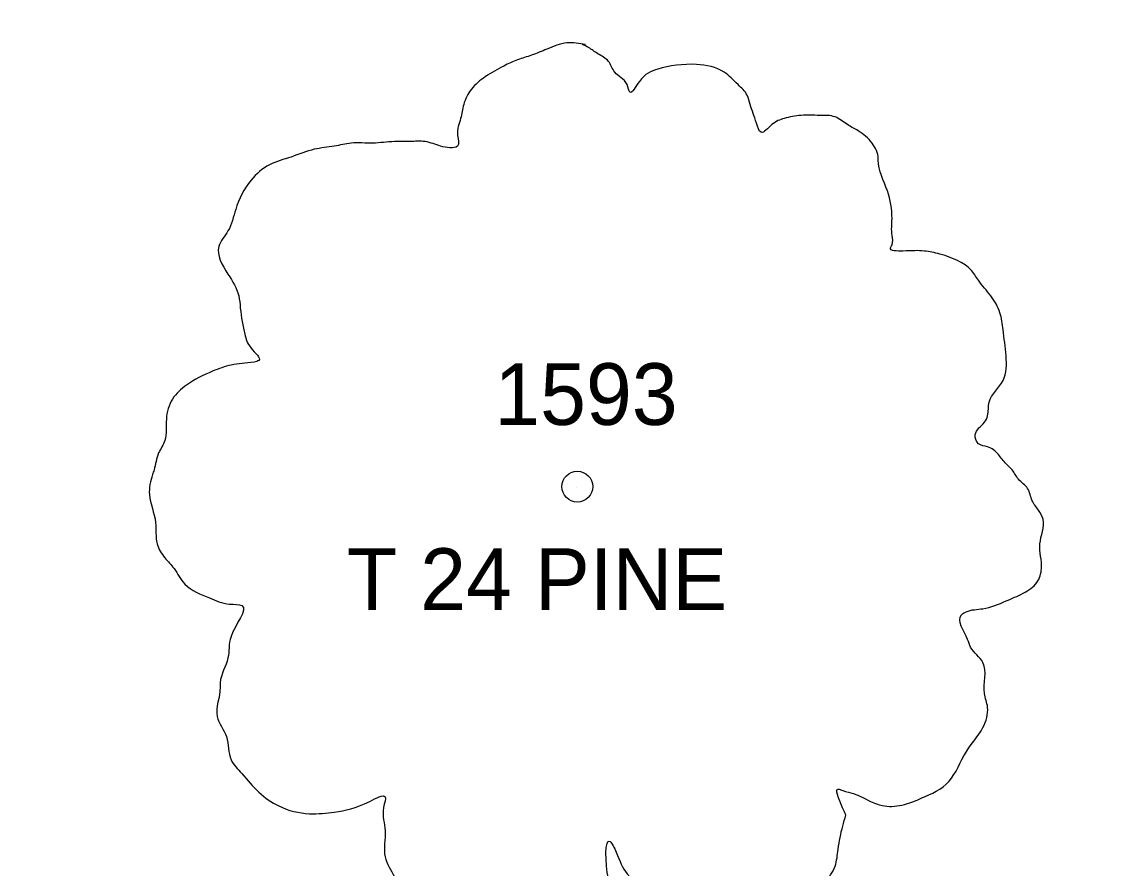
# Model space of a CAD drawing. Extents: x 1964982 to 1970452, y 1116335 to 1119906.
# Drawn here: x 1966640.09 to 1966657.58, y 1117463.46 to 1117477.19 of the extents above; entities that cross this region are included whole.
import ezdxf

# ---------------------------------------------------------------- set-up
doc = ezdxf.new("R2010")
doc.units = 0
for name, color, linetype in [('RD_EX_VEG', 7, 'Continuous'), ('RD_EX_VEG_txCode', 7, 'Continuous'), ('RD_HC_CL_Rel', 7, 'Continuous'), ('RD_PD_Final_TrvlWay', 7, 'Continuous')]:
    doc.layers.add(name, color=color, linetype=linetype)

msp = doc.modelspace()

# ---------------------------------------------------------------- linework, layer by layer
at = {"layer": 'RD_EX_VEG'}
for centre, radius in [((1966649.1, 1117469.652), 0.25), ((1966649.1, 1117469.652), 0.25), ((1966649.087, 1117469.633), 0.0001), ((1966649.087, 1117469.633), 0.0001)]:
    msp.add_circle(centre, radius, dxfattribs=at)
for points in [[(1966649.232, 1117476.819), (1966648.932, 1117476.844), (1966648.607, 1117476.744), (1966648.357, 1117476.645), (1966648.132, 1117476.57), (1966647.907, 1117476.47), (1966647.607, 1117476.295), (1966647.382, 1117476.095), (1966647.257, 1117475.845), (1966647.207, 1117475.62), (1966647.158, 1117475.345), (1966647.158, 1117475.17), (1966647.033, 1117475.145), (1966646.883, 1117475.17), (1966646.633, 1117475.245), (1966646.383, 1117475.245), (1966646.133, 1117475.245), (1966645.783, 1117475.22), (1966645.433, 1117475.22), (1966645.158, 1117475.17), (1966644.834, 1117475.12), (1966644.459, 1117474.995), (1966644.109, 1117474.87), (1966643.809, 1117474.62), (1966643.559, 1117474.146), (1966643.434, 1117473.796), (1966643.284, 1117473.546), (1966643.434, 1117473.096), (1966643.609, 1117472.746), (1966643.634, 1117472.546), (1966643.709, 1117472.122), (1966643.809, 1117471.897), (1966643.934, 1117471.697), (1966643.859, 1117471.672), (1966643.484, 1117471.622), (1966643.184, 1117471.522), (1966642.759, 1117471.297), (1966642.535, 1117471.072), (1966642.435, 1117470.747), (1966642.41, 1117470.397), (1966642.31, 1117470.197), (1966642.235, 1117469.922), (1966642.21, 1117469.847), (1966642.16, 1117469.523), (1966642.26, 1117469.073), (1966642.285, 1117468.723), (1966642.41, 1117468.498), (1966642.56, 1117468.323), (1966642.734, 1117468.073), (1966643.134, 1117467.848), (1966643.459, 1117467.748), (1966643.659, 1117467.723), (1966643.484, 1117467.224), (1966643.434, 1117466.874), (1966643.309, 1117466.474), (1966643.309, 1117466.399), (1966643.259, 1117465.924), (1966643.409, 1117465.599), (1966643.484, 1117465.225), (1966643.659, 1117465), (1966643.934, 1117464.7), (1966644.259, 1117464.475), (1966644.759, 1117464.35), (1966645.158, 1117464.375), (1966645.733, 1117464.55), (1966645.983, 1117464.625), (1966645.958, 1117464.45), (1966645.983, 1117464.075), (1966645.983, 1117463.65), (1966646.133, 1117463.325), (1966646.233, 1117463.05), (1966646.383, 1117462.801), (1966646.708, 1117462.576), (1966647.108, 1117462.501), (1966647.532, 1117462.351), (1966647.982, 1117462.276), (1966648.482, 1117462.251), (1966649.082, 1117462.401), (1966649.357, 1117462.526), (1966649.457, 1117462.701), (1966649.656, 1117463.075), (1966649.606, 1117463.3), (1966649.631, 1117463.9), (1966649.731, 1117463.725), (1966649.906, 1117463.375), (1966650.406, 1117463.075), (1966650.806, 1117462.901), (1966651.281, 1117462.751), (1966651.581, 1117462.676), (1966652.055, 1117462.751), (1966652.43, 1117462.826), (1966652.805, 1117462.951), (1966653.105, 1117463.225), (1966653.28, 1117463.5), (1966653.33, 1117463.775), (1966653.405, 1117464.15), (1966653.455, 1117464.325)], [(1966649.232, 1117476.819), (1966648.932, 1117476.844), (1966648.607, 1117476.744), (1966648.357, 1117476.645), (1966648.132, 1117476.57), (1966647.907, 1117476.47), (1966647.607, 1117476.295), (1966647.382, 1117476.095), (1966647.257, 1117475.845), (1966647.207, 1117475.62), (1966647.158, 1117475.345), (1966647.158, 1117475.17), (1966647.033, 1117475.145), (1966646.883, 1117475.17), (1966646.633, 1117475.245), (1966646.383, 1117475.245), (1966646.133, 1117475.245), (1966645.783, 1117475.22), (1966645.433, 1117475.22), (1966645.158, 1117475.17), (1966644.834, 1117475.12), (1966644.459, 1117474.995), (1966644.109, 1117474.87), (1966643.809, 1117474.62), (1966643.559, 1117474.146), (1966643.434, 1117473.796), (1966643.284, 1117473.546), (1966643.434, 1117473.096), (1966643.609, 1117472.746), (1966643.634, 1117472.546), (1966643.709, 1117472.122), (1966643.809, 1117471.897), (1966643.934, 1117471.697), (1966643.859, 1117471.672), (1966643.484, 1117471.622), (1966643.184, 1117471.522), (1966642.759, 1117471.297), (1966642.535, 1117471.072), (1966642.435, 1117470.747), (1966642.41, 1117470.397), (1966642.31, 1117470.197), (1966642.235, 1117469.922), (1966642.21, 1117469.847), (1966642.16, 1117469.523), (1966642.26, 1117469.073), (1966642.285, 1117468.723), (1966642.41, 1117468.498), (1966642.56, 1117468.323), (1966642.734, 1117468.073), (1966643.134, 1117467.848), (1966643.459, 1117467.748), (1966643.659, 1117467.723), (1966643.484, 1117467.224), (1966643.434, 1117466.874), (1966643.309, 1117466.474), (1966643.309, 1117466.399), (1966643.259, 1117465.924), (1966643.409, 1117465.599), (1966643.484, 1117465.225), (1966643.659, 1117465), (1966643.934, 1117464.7), (1966644.259, 1117464.475), (1966644.759, 1117464.35), (1966645.158, 1117464.375), (1966645.733, 1117464.55), (1966645.983, 1117464.625), (1966645.958, 1117464.45), (1966645.983, 1117464.075), (1966645.983, 1117463.65), (1966646.133, 1117463.325), (1966646.233, 1117463.05), (1966646.383, 1117462.801), (1966646.708, 1117462.576), (1966647.108, 1117462.501), (1966647.532, 1117462.351), (1966647.982, 1117462.276), (1966648.482, 1117462.251), (1966649.082, 1117462.401), (1966649.357, 1117462.526), (1966649.457, 1117462.701), (1966649.656, 1117463.075), (1966649.606, 1117463.3), (1966649.631, 1117463.9), (1966649.731, 1117463.725), (1966649.906, 1117463.375), (1966650.406, 1117463.075), (1966650.806, 1117462.901), (1966651.281, 1117462.751), (1966651.581, 1117462.676), (1966652.055, 1117462.751), (1966652.43, 1117462.826), (1966652.805, 1117462.951), (1966653.105, 1117463.225), (1966653.28, 1117463.5), (1966653.33, 1117463.775), (1966653.405, 1117464.15), (1966653.455, 1117464.325)], [(1966653.455, 1117464.325), (1966653.38, 1117464.5), (1966653.33, 1117464.75), (1966653.405, 1117464.725), (1966653.58, 1117464.675), (1966653.855, 1117464.55), (1966654.08, 1117464.475), (1966654.404, 1117464.5), (1966654.679, 1117464.6), (1966655.129, 1117464.875), (1966655.404, 1117465.349), (1966655.679, 1117465.749), (1966655.754, 1117466.074), (1966655.704, 1117466.299), (1966655.679, 1117466.799), (1966655.479, 1117467.049), (1966655.429, 1117467.174), (1966655.329, 1117467.573), (1966655.404, 1117467.623), (1966655.679, 1117467.673), (1966656.054, 1117467.798), (1966656.329, 1117467.923), (1966656.553, 1117468.098), (1966656.628, 1117468.323), (1966656.603, 1117468.723), (1966656.653, 1117469.123), (1966656.578, 1117469.273), (1966656.478, 1117469.423), (1966656.403, 1117469.623), (1966656.254, 1117469.772), (1966656.154, 1117469.922), (1966656.054, 1117470.022), (1966655.929, 1117470.172), (1966655.754, 1117470.297), (1966655.604, 1117470.347), (1966655.554, 1117470.497), (1966655.704, 1117470.697), (1966655.754, 1117470.797), (1966655.779, 1117471.022), (1966656.004, 1117471.372), (1966656.054, 1117471.772), (1966656.004, 1117472.196), (1966655.954, 1117472.471), (1966655.804, 1117472.746), (1966655.604, 1117472.996), (1966655.479, 1117473.171), (1966655.304, 1117473.296), (1966654.979, 1117473.421), (1966654.729, 1117473.471), (1966654.379, 1117473.471), (1966654.179, 1117473.521), (1966654.204, 1117473.571), (1966654.204, 1117473.721), (1966654.204, 1117473.996), (1966654.129, 1117474.445), (1966653.98, 1117474.945), (1966653.98, 1117474.97), (1966653.88, 1117475.22), (1966653.655, 1117475.42), (1966653.48, 1117475.52), (1966653.28, 1117475.645), (1966653.03, 1117475.67), (1966652.73, 1117475.67), (1966652.455, 1117475.62), (1966652.255, 1117475.52), (1966652.08, 1117475.395), (1966652.005, 1117475.545), (1966651.905, 1117475.845), (1966651.855, 1117475.995), (1966651.706, 1117476.17), (1966651.481, 1117476.37), (1966651.031, 1117476.495), (1966650.406, 1117476.42), (1966650.106, 1117476.22), (1966649.956, 1117476.045), (1966649.906, 1117476.17), (1966649.706, 1117476.37), (1966649.606, 1117476.545), (1966649.432, 1117476.67), (1966649.282, 1117476.769), (1966649.182, 1117476.819)], [(1966653.455, 1117464.325), (1966653.38, 1117464.5), (1966653.33, 1117464.75), (1966653.405, 1117464.725), (1966653.58, 1117464.675), (1966653.855, 1117464.55), (1966654.08, 1117464.475), (1966654.404, 1117464.5), (1966654.679, 1117464.6), (1966655.129, 1117464.875), (1966655.404, 1117465.349), (1966655.679, 1117465.749), (1966655.754, 1117466.074), (1966655.704, 1117466.299), (1966655.679, 1117466.799), (1966655.479, 1117467.049), (1966655.429, 1117467.174), (1966655.329, 1117467.573), (1966655.404, 1117467.623), (1966655.679, 1117467.673), (1966656.054, 1117467.798), (1966656.329, 1117467.923), (1966656.553, 1117468.098), (1966656.628, 1117468.323), (1966656.603, 1117468.723), (1966656.653, 1117469.123), (1966656.578, 1117469.273), (1966656.478, 1117469.423), (1966656.403, 1117469.623), (1966656.254, 1117469.772), (1966656.154, 1117469.922), (1966656.054, 1117470.022), (1966655.929, 1117470.172), (1966655.754, 1117470.297), (1966655.604, 1117470.347), (1966655.554, 1117470.497), (1966655.704, 1117470.697), (1966655.754, 1117470.797), (1966655.779, 1117471.022), (1966656.004, 1117471.372), (1966656.054, 1117471.772), (1966656.004, 1117472.196), (1966655.954, 1117472.471), (1966655.804, 1117472.746), (1966655.604, 1117472.996), (1966655.479, 1117473.171), (1966655.304, 1117473.296), (1966654.979, 1117473.421), (1966654.729, 1117473.471), (1966654.379, 1117473.471), (1966654.179, 1117473.521), (1966654.204, 1117473.571), (1966654.204, 1117473.721), (1966654.204, 1117473.996), (1966654.129, 1117474.445), (1966653.98, 1117474.945), (1966653.98, 1117474.97), (1966653.88, 1117475.22), (1966653.655, 1117475.42), (1966653.48, 1117475.52), (1966653.28, 1117475.645), (1966653.03, 1117475.67), (1966652.73, 1117475.67), (1966652.455, 1117475.62), (1966652.255, 1117475.52), (1966652.08, 1117475.395), (1966652.005, 1117475.545), (1966651.905, 1117475.845), (1966651.855, 1117475.995), (1966651.706, 1117476.17), (1966651.481, 1117476.37), (1966651.031, 1117476.495), (1966650.406, 1117476.42), (1966650.106, 1117476.22), (1966649.956, 1117476.045), (1966649.906, 1117476.17), (1966649.706, 1117476.37), (1966649.606, 1117476.545), (1966649.432, 1117476.67), (1966649.282, 1117476.769), (1966649.182, 1117476.819)]]:
    msp.add_spline(points, degree=3, dxfattribs=at)
at = {"layer": 'RD_HC_CL_Rel'}
msp.add_arc((1966373.74, 1118527.456), 1145.915, 281.904723, 295.046328, dxfattribs=at)
at = {"layer": 'RD_PD_Final_TrvlWay'}
for radius in [1134.915, 1156.915]:
    msp.add_arc((1966373.74, 1118527.456), radius, 281.904723, 295.046328, dxfattribs=at)

# ---------------------------------------------------------------- texts
at = {"layer": 'RD_EX_VEG_txCode'}
for s, p in [('1593', (1966647.753, 1117470.652)), ('1593', (1966647.753, 1117470.652)), ('T 24 PINE', (1966645.363, 1117467.652)), ('T 24 PINE', (1966645.363, 1117467.652))]:
    msp.add_text(s, height=1, dxfattribs=at).set_placement(p)

doc.saveas('drawing.dxf')
